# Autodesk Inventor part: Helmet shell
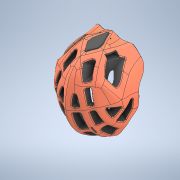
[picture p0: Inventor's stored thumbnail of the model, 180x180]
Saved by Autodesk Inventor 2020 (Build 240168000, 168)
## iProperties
Created: 2021-10
Part Number: Helmet shell
Material: Steel
Document SubType Name: Modeling
Designer: bruno
Density: 7.85 g/cm^3
Appearance: Transparent - Bleu
Author: bruno
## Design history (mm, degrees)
node "Helma"
sketch "Esquisse2"
  geometry: L1 (119.454, 20.359)-(103.121, 95.691); L2 (136.404, 97.672)-(103.121, 95.691); L3 (134.366, 108.053)-(134.529, 107.224); L4 (119.454, 20.359)-(149.292, 32.024); L5 (136.404, 97.672)-(149.292, 32.024); L6 (151.558, 20.48)-(151.582, 20.359); 13 further points
  constraints: 12 end point, 14 other
extrude "Extrusion2" join sketch "Esquisse2" stored distance "d2" = 40; taper "d3" = 0 deg
fillet "Congé5" dims "d14" = 4
fillet "Congé6" dims "d15" = 4
sketch "Esquisse4"
  geometry: L1 (-45.835, 127.688)-(-45.835, 116.43) reference; L2 (-80.517, 127.688)-(-45.835, 127.688) reference; L3 (-80.517, 116.43)-(-80.517, 127.688) reference; L4 (-45.835, 116.43)-(-80.517, 116.43) reference; 1 further point
extrude "Extrusion3" cut sketch "Esquisse4" distance "d16" = 1000; taper "d17" = 0 deg
sketch "Esquisse5"
  geometry: L1 (-19.454, -58.928)-(-19.454, -42.462) reference; L2 (20.546, -42.462)-(20.546, -58.928) reference; 11 further points
  constraints: 12 other
extrude "Extrusion4" join sketch "Esquisse5" distance "d18" = 3; taper "d19" = 0 deg
node "Solide1"
node "Boucle projetée1"
node "Boucle projetée2"
node "Boucle projetée8"
node "Boucle projetée9"
